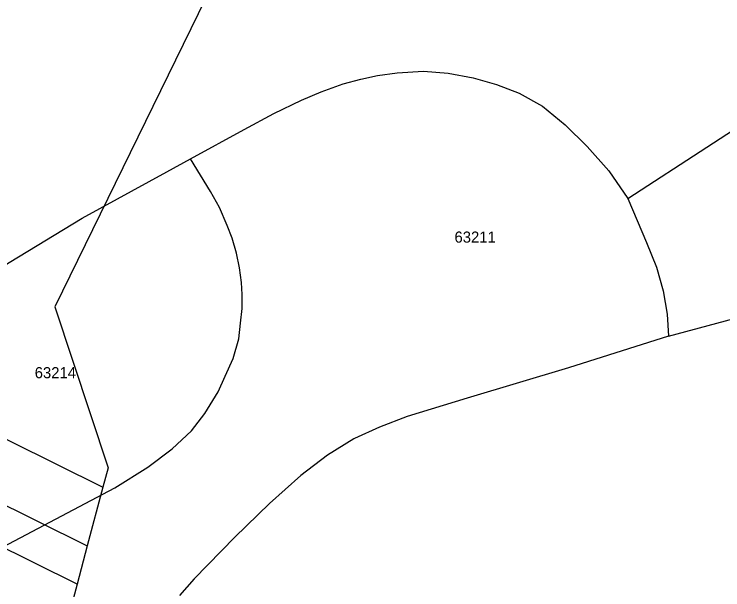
# Model space of a CAD drawing. Extents: x -546762 to -540209, y -1046851 to -1035694.
# Drawn here: x -542624.6 to -542465, y -1040164.6 to -1040034.9 of the extents above; entities that cross this region are included whole.
import ezdxf

# ---------------------------------------------------------------- set-up
doc = ezdxf.new("R2010")
doc.units = 0
for name, color, linetype in [('Vrstva 1', 7, 'Continuous'), ('Vrstva 52', 7, 'Continuous'), ('Vrstva 53', 7, 'Continuous')]:
    doc.layers.add(name, color=color, linetype=linetype)

msp = doc.modelspace()

# ---------------------------------------------------------------- linework, layer by layer
at = {"layer": 'Vrstva 1'}
for points in [[(-542557.72, -1039982.5), (-542615.49, -1040100.81)], [(-542610.45, -1040163.32), (-542755.68, -1040091.32)], [(-542615.49, -1040100.81), (-542603.48, -1040137.1)], [(-542646.67, -1040120.68), (-542604.65, -1040141.51)], [(-542653.18, -1040132.42), (-542608.17, -1040154.73)], [(-542603.48, -1040137.1), (-542604.65, -1040141.51)], [(-542604.65, -1040141.51), (-542608.17, -1040154.73)], [(-542608.17, -1040154.73), (-542610.45, -1040163.32)], [(-542610.45, -1040163.32), (-542622.01, -1040206.8)]]:
    msp.add_lwpolyline(points, dxfattribs=at)
at = {"layer": 'Vrstva 52'}
for points in [[(-542486.46, -1040076.42), (-542450.86, -1040053.26), (-542444.8, -1040048.4), (-542439.25, -1040043.78)], [(-542584.96, -1040067.51), (-542572.85, -1040060.91), (-542566.19, -1040057.24), (-542559.96, -1040054.25), (-542555.52, -1040052.37), (-542550.57, -1040050.58), (-542546.56, -1040049.55), (-542542.8, -1040048.7), (-542538.36, -1040048.1), (-542532.47, -1040047.76), (-542526.93, -1040048.19), (-542521.29, -1040049.23), (-542516, -1040050.77), (-542510.88, -1040052.65), (-542505.67, -1040055.64), (-542500.55, -1040059.82), (-542495.6, -1040064.69), (-542490.74, -1040070.16), (-542486.46, -1040076.42)], [(-542666.8, -1040117.35), (-542633.38, -1040095.5), (-542625.77, -1040090.87), (-542609.33, -1040080.86), (-542590.25, -1040070.4), (-542584.96, -1040067.51)], [(-542601.96, -1040141.62), (-542594.56, -1040137), (-542589.03, -1040132.82), (-542584.7, -1040128.78), (-542581.71, -1040124.9), (-542578.73, -1040119.97), (-542577.13, -1040116.5), (-542575.29, -1040112.49), (-542574.08, -1040108.03), (-542573.65, -1040104.52), (-542573.31, -1040101.19), (-542573.31, -1040098.03), (-542573.48, -1040095.39), (-542573.91, -1040092.06), (-542574.59, -1040088.73), (-542575.53, -1040085.39), (-542576.64, -1040082.49), (-542578.43, -1040078.48), (-542580.4, -1040074.81), (-542584.96, -1040067.51)], [(-542477.31, -1040107.43), (-542396.02, -1040085.62), (-542391.45, -1040084.27), (-542385.31, -1040082.46), (-542378.25, -1040080.39), (-542356.03, -1040073.85), (-542343.48, -1040068.62)], [(-542486.46, -1040076.42), (-542482.24, -1040086.36), (-542479.99, -1040091.89), (-542478.5, -1040097.27), (-542477.61, -1040102.5), (-542477.31, -1040107.43)], [(-542477.31, -1040107.43), (-542499.77, -1040114.6), (-542522.65, -1040121.43), (-542536.13, -1040125.53), (-542542.37, -1040127.93), (-542548, -1040130.49), (-542548.18, -1040130.6), (-542554.06, -1040134.24), (-542560.07, -1040138.88), (-542567.13, -1040145.15), (-542574.97, -1040152.74), (-542584.12, -1040162.15), (-542587.43, -1040165.91)], [(-542652.53, -1040168.27), (-542601.96, -1040141.62)]]:
    msp.add_lwpolyline(points, dxfattribs=at)

# ---------------------------------------------------------------- texts
at = {"layer": 'Vrstva 53'}
for s, p in [('63211', (-542525.48, -1040086.37)), ('63214', (-542620.02, -1040116.93))]:
    msp.add_text(s, height=2.5, dxfattribs=at).set_placement(p)

doc.saveas('drawing.dxf')
